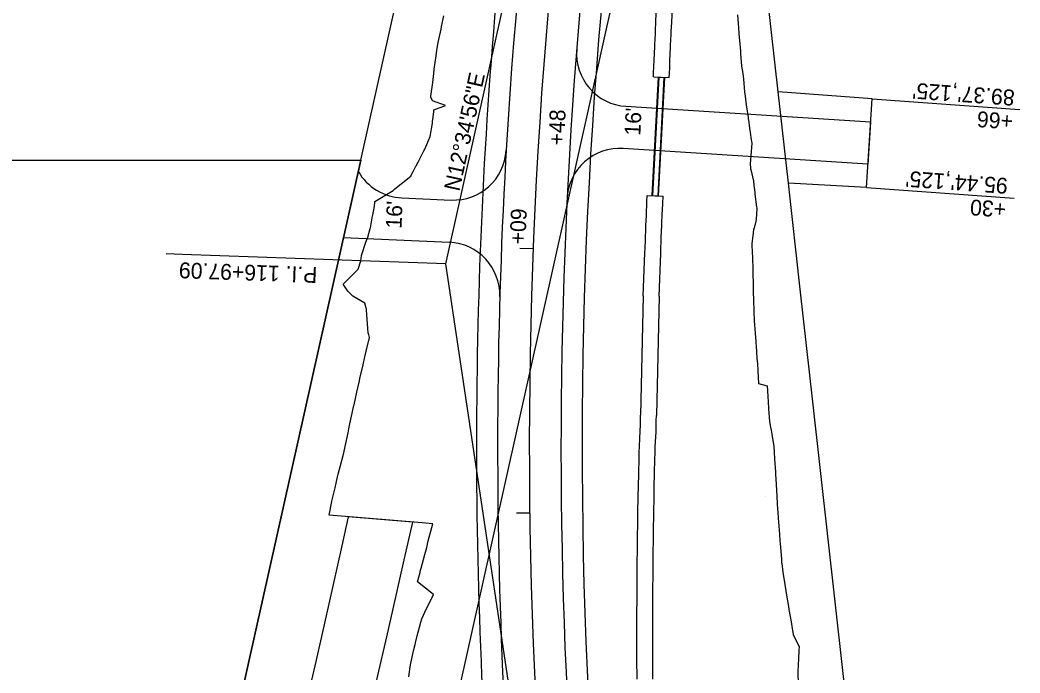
# Model space of a CAD drawing. Extents: x 609264 to 611265, y 427753 to 431566.
# Drawn here: x 610695.3 to 611074.1, y 429817.8 to 430065 of the extents above; entities that cross this region are included whole.
import ezdxf

# ---------------------------------------------------------------- set-up
doc = ezdxf.new("R2010")
doc.units = 0
for name, color, linetype in [('R_Drainage', 7, 'Continuous'), ('R_Drive', 7, 'Continuous'), ('R_Drive Annot', 7, 'Continuous'), ('R_Drive Annot Stage 2', 7, 'Continuous'), ('R_Drive Stage 2', 7, 'Continuous'), ('R_Horz Alg', 7, 'Continuous'), ('R_Horz Alg Annot', 7, 'Continuous'), ('R_Horz Alg Station', 7, 'Continuous'), ('R_Horz Alg Station Annot', 7, 'Continuous'), ('R_Horz Bearings', 7, 'Continuous'), ('R_Obliterate', 7, 'Continuous'), ('R_Proposed Const Limits', 7, 'Continuous'), ('R_Proposed Const Limits S2', 7, 'Continuous'), ('R_Proposed Road', 7, 'Continuous'), ('R_Proposed Road Stage 2', 7, 'Continuous'), ('R_Proposed Shoulder', 7, 'Continuous'), ('R_Proposed Shoulder Stage 2', 7, 'Continuous'), ('R_Restraining Conditions', 7, 'Continuous'), ('R_ROW', 7, 'Continuous'), ('R_ROW Annot', 7, 'Continuous'), ('R_Temp Easement', 7, 'Continuous'), ('S_EXIST_ROW', 7, 'Continuous')]:
    doc.layers.add(name, color=color, linetype=linetype)

msp = doc.modelspace()

# ---------------------------------------------------------------- linework, layer by layer
at = {"layer": 'R_Drainage'}
for p, q in [((610937.04, 430043.38), (610934.7, 429998.49)), ((610937.25, 430043.37), (610934.91, 429998.48)), ((610935.25, 430043.45), (610941.25, 430043.16)), ((610939.25, 430043.26), (610936.91, 429998.38)), ((610937.04, 430043.38), (610939.46, 430043.25)), ((610939.46, 430043.25), (610937.11, 429998.37)), ((610932.91, 429998.59), (610938.9, 429998.23)), ((610934.7, 429998.49), (610937.11, 429998.37)), ((610931.44, 429960.6), (610930.38, 429915.36)), ((610937.43, 429960.47), (610936.38, 429915.23))]:
    msp.add_line(p, q, dxfattribs=at)
for points in [[(610935.25, 430043.45), (610935.34, 430045.09), (610935.43, 430047.18), (610935.54, 430049.96), (610935.76, 430054.84), (610935.8, 430055.77), (610935.99, 430059.73), (610936.04, 430060.89), (610936.21, 430064.36), (610936.23, 430064.63), (610936.48, 430069.51)], [(610941.25, 430043.16), (610941.34, 430044.8), (610941.42, 430046.93), (610941.54, 430049.7), (610941.75, 430054.57), (610941.79, 430055.49), (610941.98, 430059.45), (610942.03, 430060.59), (610942.21, 430064.06), (610942.22, 430064.32), (610942.47, 430069.19)], [(610931.44, 429960.6), (610932.02, 429976.79), (610932.09, 429978.6), (610932.21, 429981.67), (610932.22, 429981.93), (610932.39, 429986.24), (610932.4, 429986.55), (610932.43, 429987.18), (610932.5, 429989.07), (610932.58, 429990.8), (610932.6, 429991.44), (610932.79, 429995.71), (610932.79, 429995.76), (610932.81, 429996.32), (610932.91, 429998.59)], [(610937.43, 429960.47), (610938.02, 429976.57), (610938.09, 429978.37), (610938.2, 429981.44), (610938.21, 429981.69), (610938.38, 429986), (610938.4, 429986.31), (610938.42, 429986.93), (610938.5, 429988.83), (610938.57, 429990.55), (610938.6, 429991.18), (610938.78, 429995.45), (610938.78, 429995.5), (610938.9, 429998.23)], [(610930.29, 429909.16), (610930.3, 429909.91), (610930.32, 429911.07), (610930.35, 429913.29), (610930.38, 429915.36)], [(610936.29, 429909.07), (610936.3, 429909.82), (610936.32, 429910.98), (610936.35, 429913.19), (610936.38, 429915.23)], [(610929.06, 429815.46), (610929.05, 429818.27), (610929.04, 429820.36), (610929.03, 429823.95), (610929.03, 429825.26), (610929.02, 429830.16), (610929.02, 429831.87), (610929.02, 429832.35), (610929.02, 429832.56), (610929.03, 429835.06), (610929.04, 429839.95), (610929.04, 429841.16), (610929.06, 429844.85), (610929.08, 429849.74), (610929.08, 429849.77), (610929.12, 429854.64), (610929.15, 429857.93), (610929.15, 429858.37), (610929.16, 429859.53), (610929.22, 429864.43), (610929.25, 429866.97), (610929.28, 429869.32), (610929.34, 429874.21), (610929.36, 429875.57), (610929.42, 429879.1), (610929.51, 429883.99), (610929.51, 429884.17), (610929.6, 429888.88), (610929.68, 429892.76), (610929.7, 429893.77), (610929.81, 429898.66), (610929.87, 429901.36), (610929.93, 429903.65), (610930.3, 429909.41)], [(610935.06, 429815.49), (610935.05, 429818.3), (610935.04, 429820.38), (610935.03, 429823.96), (610935.03, 429825.27), (610935.02, 429830.16), (610935.02, 429831.87), (610935.02, 429832.35), (610935.02, 429832.55), (610935.03, 429835.05), (610935.04, 429839.93), (610935.04, 429841.14), (610935.06, 429844.82), (610935.08, 429849.71), (610935.08, 429849.73), (610935.12, 429854.59), (610935.15, 429857.88), (610935.15, 429858.32), (610935.16, 429859.47), (610935.22, 429864.36), (610935.25, 429866.9), (610935.28, 429869.24), (610935.34, 429874.12), (610935.36, 429875.48), (610935.42, 429879), (610935.5, 429883.89), (610935.51, 429884.06), (610935.6, 429888.77), (610935.68, 429892.64), (610935.7, 429893.64), (610935.81, 429898.53), (610935.87, 429901.21), (610935.92, 429903.38), (610936.29, 429909.02)]]:
    msp.add_lwpolyline(points, dxfattribs=at)
at = {"layer": 'R_Drive'}
for p, q in [((611017.52, 430026.33), (610924.84, 430032.3)), ((611017.52, 430026.33), (611016.49, 430010.37)), ((611016.49, 430010.37), (610923.81, 430016.33))]:
    msp.add_line(p, q, dxfattribs=at)
for centre, start, end in [((610926.13, 430052.26), 175.4614, 266.3158), ((610922.53, 429996.38), 86.3158, 177.1701)]:
    msp.add_arc(centre, 20, start, end, dxfattribs=at)
at = {"layer": 'R_Drive Stage 2'}
for p, q in [((610823.47, 430007.66), (610817.88, 429982.61)), ((610839.93, 429997.66), (610858.66, 429996.83)), ((610817.88, 429982.61), (610857.96, 429980.85))]:
    msp.add_line(p, q, dxfattribs=at)
for centre, start, end in [((610859.54, 430016.81), 267.4858, 356.6596), ((610840.8, 430017.64), 209.9159, 267.4858), ((610857.08, 429960.87), 358.3119, 87.4858)]:
    msp.add_arc(centre, 20, start, end, dxfattribs=at)
at = {"layer": 'R_Horz Alg'}
msp.add_arc((612798.1, 429903.66), 1909.86, 167.41778, 188.50997, dxfattribs=at)
at = {"layer": 'R_Horz Alg Annot'}
for p, q in [((610856.65, 429972.69), (610934.1, 430319.71)), ((610909.26, 429621.04), (610856.65, 429972.69))]:
    msp.add_line(p, q, dxfattribs=at)
at = {"layer": 'R_Horz Alg Station'}
for points in [[(610856.65, 429972.69), (610756.71, 429976.24), (610750.71, 429976.45)], [(610884.71, 429978.65), (610889.7, 429978.45)], [(610883.4, 429878.41), (610888.4, 429878.47)]]:
    msp.add_lwpolyline(points, dxfattribs=at)
at = {"layer": 'R_Obliterate'}
for p, q in [((610819.66, 429876.89), (610817.21, 429865.94)), ((610844.1, 429874.92), (610819.66, 429876.89))]:
    msp.add_line(p, q, dxfattribs=at)
for points in [[(610812.96, 429735.41), (610814.75, 429743.71), (610817.91, 429758.35), (610821.1, 429772.98), (610824.35, 429787.61), (610827.65, 429802.18), (610830.94, 429816.8), (610834.24, 429831.41), (610837.58, 429846.02), (610840.87, 429860.64), (610844.1, 429874.92)], [(610817.21, 429865.94), (610813.98, 429851.31), (610810.7, 429836.68), (610807.36, 429822.08), (610804.03, 429807.47), (610800.76, 429792.81), (610797.52, 429778.17), (610794.28, 429763.55), (610791.03, 429748.91), (610787.8, 429734.28), (610784.54, 429719.65), (610781.35, 429705.03), (610778.18, 429690.38), (610774.95, 429675.75), (610772.86, 429666.54), (610770.67, 429656.14), (610767.8, 429641.34), (610765.35, 429626.4), (610762.85, 429611.63), (610760.33, 429596.4), (610758.08, 429581.46), (610756.13, 429566.21), (610754.43, 429550.93), (610753.64, 429540.31)]]:
    msp.add_lwpolyline(points, dxfattribs=at)
at = {"layer": 'R_Proposed Const Limits'}
for points in [[(610967.12, 430066.89), (610967.43, 430062.03), (610967.45, 430061.78), (610967.77, 430058.31), (610967.87, 430057.17), (610968.2, 430053.23), (610968.24, 430052.31), (610968.66, 430047.46), (610969.07, 430044.69), (610969.37, 430042.59), (610969.76, 430037.74), (610969.97, 430036.16), (610970.42, 430032.89), (610971.1, 430028.03), (610971.15, 430027.63), (610971.34, 430026.29), (610971.51, 430025), (610971.75, 430023.18), (610971.86, 430022.45), (610972.29, 430019.62), (610972.37, 430019.11), (610972.49, 430018.34), (610972.15, 430013.56), (610971.91, 430010.7), (610972.01, 430008.77), (610972.08, 430008.51), (610972.12, 430008.38), (610973.15, 430003.91), (610973.19, 430003.56), (610973.25, 430002.97), (610973.29, 430002.66), (610973.34, 430002.19), (610973.49, 430000.8), (610973.63, 429999.62), (610973.69, 429999.09), (610974.36, 429994.27), (610974.44, 429993.72), (610974.45, 429993.67), (610974.13, 429989.5), (610973.99, 429988.88), (610973.62, 429987.21), (610973.21, 429985.36), (610973.08, 429984.76), (610973.01, 429984.45), (610972.58, 429980.24), (610972.59, 429979.99), (610972.69, 429976.97), (610972.76, 429975.2), (610972.87, 429970.41), (610972.93, 429968.55), (610973.03, 429965.62), (610973.09, 429960.83), (610973.11, 429960.14), (610973.19, 429957.78), (610973.25, 429956.05), (610973.33, 429953.71), (610973.39, 429952.03), (610973.4, 429951.73), (610973.41, 429951.54), (610973.42, 429951.26), (610973.79, 429946.47), (610974.05, 429943.31), (610974.08, 429942.7), (610974.12, 429941.69), (610974.49, 429936.9), (610974.67, 429934.9), (610974.85, 429932.12), (610975.05, 429927.35)], [(610975.05, 429927.35), (610978.33, 429926.47), (610978.56, 429922.54), (610978.83, 429918.09), (610978.84, 429917.77), (610979.2, 429913.01), (610979.65, 429910.84), (610979.86, 429909.71), (610980.12, 429908.24), (610980.91, 429903.48), (610981.02, 429901.35), (610981.17, 429898.73), (610981.45, 429893.97), (610981.5, 429892.99), (610981.72, 429889.22), (610982.02, 429884.63), (610982.03, 429884.46), (610982.32, 429879.71), (610982.38, 429878.75), (610982.56, 429876.28), (610982.65, 429874.96), (610982.98, 429870.21), (610983.16, 429867.94), (610983.37, 429865.47), (610983.75, 429860.72), (610983.83, 429859.6), (610983.85, 429859.17), (610984.25, 429855.98), (610984.99, 429851.28), (610985, 429851.25), (610985.77, 429846.53), (610986.37, 429842.97), (610986.57, 429841.8), (610987.38, 429837.09), (610987.79, 429834.68), (610987.83, 429834.49), (610987.91, 429834.02), (610988.2, 429832.37), (610990.41, 429827.72), (610990.38, 429826.45), (610990.26, 429822.97), (610990.06, 429820.94), (610989.9, 429818.21), (610989.9, 429818.09), (610990.06, 429813.47)], [(610977.77, 429884.42), (610977.77, 429884.42)], [(610842.62, 429816.38), (610843.1, 429820.16), (610843.39, 429821.54), (610844.57, 429826.71), (610844.98, 429828.52), (610845.1, 429829.03), (610845.15, 429829.24), (610845.8, 429831.88), (610847.11, 429837.04), (610847.6, 429838.32), (610849.29, 429842.23), (610852, 429847.41), (610852.02, 429847.44), (610845.89, 429852.35), (610846.85, 429855.81), (610846.97, 429856.28), (610847.32, 429857.5), (610848.74, 429862.64), (610849.4, 429865.3), (610850, 429867.76), (610851.38, 429872.89), (610851.69, 429874.31), (610847.7, 429874.63)]]:
    msp.add_lwpolyline(points, dxfattribs=at)
at = {"layer": 'R_Proposed Const Limits S2'}
for points in [[(610851.61, 430034.32), (610850.97, 430035.78), (610851.01, 430036.21), (610851.66, 430041.28), (610852.09, 430044.7), (610852.27, 430046.36), (610852.95, 430051.43), (610853.28, 430053.62), (610853.71, 430056.49), (610854.81, 430061.53), (610855.02, 430062.48), (610855.93, 430066.56)], [(610847.7, 429874.63), (610812.46, 429877.47), (610813.46, 429882.68), (610813.5, 429882.87), (610814.66, 429887.89), (610815.62, 429892.01), (610815.86, 429893.09), (610817.23, 429898.28), (610817.95, 429901.14), (610818.48, 429903.47), (610819.59, 429908.65), (610819.91, 429910.24), (610820.15, 429911.47), (610820.63, 429913.82), (610821.79, 429918.99), (610821.87, 429919.33), (610822.94, 429924.15), (610823.89, 429928.4), (610824.1, 429929.31), (610825.28, 429934.46), (610825.98, 429937.45), (610826.48, 429939.6), (610827.67, 429944.74), (610827.43, 429945.84), (610827.18, 429946.5), (610826.97, 429949.92), (610826.64, 429955.09), (610826.58, 429955.39), (610826.54, 429955.6), (610826.47, 429955.92), (610825.89, 429957.75), (610821.39, 429960.41), (610819.5, 429962.33), (610817.8, 429964.95), (610818.52, 429965.68), (610823.47, 429970.7), (610824.42, 429973.83), (610824.66, 429975.83), (610826.3, 429980.94), (610827.07, 429982.82), (610828.03, 429986.04), (610828.08, 429986.3), (610828.92, 429990.83), (610828.98, 429991.16), (610829.1, 429991.82), (610829.46, 429993.81), (610829.7, 429995.62), (610829.75, 429996.29), (610836.68, 430000.47), (610837.32, 430001.08), (610843.4, 430005.91), (610843.68, 430006.46), (610844.31, 430007.68), (610845.06, 430009.12), (610845.31, 430009.6), (610845.47, 430009.92), (610845.79, 430010.54), (610845.98, 430010.9), (610848.35, 430015.48), (610848.52, 430015.88), (610849.41, 430017.88), (610850.74, 430020.87), (610851.53, 430025.93), (610851.61, 430026.74), (610851.68, 430027.29), (610852.04, 430030.24), (610852.13, 430031.01), (610856.52, 430032.64), (610851.61, 430034.32)]]:
    msp.add_lwpolyline(points, dxfattribs=at)
at = {"layer": 'R_Proposed Road'}
for radius, start in [(1897.86, 170.45369), (1921.86, 176.59591)]:
    msp.add_arc((612798.1, 429903.66), radius, start, 188.50997, dxfattribs=at)
at = {"layer": 'R_Proposed Road Stage 2'}
msp.add_arc((612798.1, 429903.66), 1921.86, 167.41778, 176.59591, dxfattribs=at)
at = {"layer": 'R_Proposed Shoulder'}
for radius, start in [(1889.86, 167.41778), (1929.86, 177.97809)]:
    msp.add_arc((612798.1, 429903.66), radius, start, 188.50997, dxfattribs=at)
at = {"layer": 'R_Proposed Shoulder Stage 2'}
msp.add_arc((612798.1, 429903.66), 1929.86, 167.41778, 177.97809, dxfattribs=at)
at = {"layer": 'R_Restraining Conditions'}
for p, q in [((609362.96, 430011.86), (610824.41, 430011.86)), ((610824.41, 430011.86), (610757.09, 429710.26))]:
    msp.add_line(p, q, dxfattribs=at)
at = {"layer": 'R_ROW'}
msp.add_lwpolyline([(611015.56, 429741.88), (610995.63, 429920.47), (610990.88, 429963.12), (610986.42, 430003.18), (610982.55, 430037.76), (610977.26, 430085.17), (610983.75, 430219.78), (610992.27, 430396.71), (610992.27, 430396.71)], dxfattribs=at)
at = {"layer": 'R_ROW Annot'}
for p, q in [((611018.09, 430035.14), (611074.11, 430031.15)), ((611015.92, 430001.56), (611071.95, 429997.57))]:
    msp.add_line(p, q, dxfattribs=at)
at = {"layer": 'R_Temp Easement'}
for p, q in [((611018.09, 430035.14), (610982.55, 430037.76)), ((611015.92, 430001.56), (611018.09, 430035.14)), ((611015.92, 430001.56), (610986.42, 430003.18))]:
    msp.add_line(p, q, dxfattribs=at)
at = {"layer": 'S_EXIST_ROW'}
for p, q in [((610757.09, 429710.26), (610942.43, 430540.66)), ((610822.59, 429636.49), (611020.51, 430523.23))]:
    msp.add_line(p, q, dxfattribs=at)

# ---------------------------------------------------------------- texts
at = {"layer": 'R_Drive Annot'}
for s, rotation, p in [('+48', 87.7761, (610901.48, 430017.42)), ("16'", 87.2646, (610930.29, 430021.13))]:
    msp.add_text(s, height=6, rotation=rotation, dxfattribs=at).set_placement(p)
at = {"layer": 'R_Drive Annot Stage 2'}
for s, rotation, p in [("16'", 87.3435, (610839.81, 429985.9)), ('+09', 87.7761, (610886.79, 429979.93))]:
    msp.add_text(s, height=6, rotation=rotation, dxfattribs=at).set_placement(p)
at = {"layer": 'R_Horz Alg Station Annot'}
msp.add_text('P.I. 116+97.09', height=6, rotation=177.9639, dxfattribs=at).set_placement((610808.06, 429971.41))
at = {"layer": 'R_Horz Bearings'}
msp.add_text('N12%%d34\'56"E', height=6, rotation=77.6114, dxfattribs=at).set_placement((610861.74, 429999.87))
at = {"layer": 'R_ROW Annot'}
for s, p in [("89.37',125'", (611072.28, 430038.49)), ('+66', (611071.64, 430029.51)), ("95.44',125'", (611069.67, 430005.12)), ('+30', (611069.03, 429996.14))]:
    msp.add_text(s, height=6, rotation=175.9258, dxfattribs=at).set_placement(p)

doc.saveas('drawing.dxf')
